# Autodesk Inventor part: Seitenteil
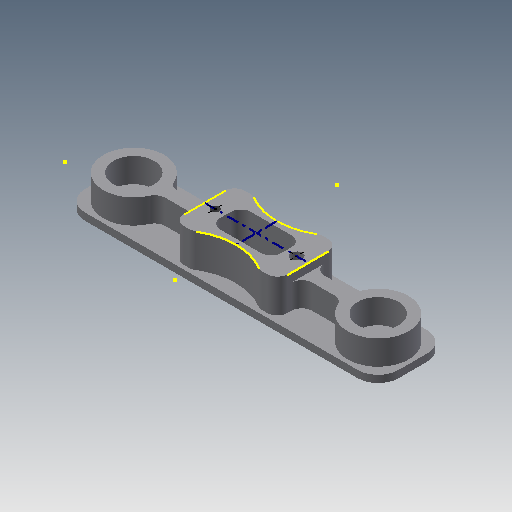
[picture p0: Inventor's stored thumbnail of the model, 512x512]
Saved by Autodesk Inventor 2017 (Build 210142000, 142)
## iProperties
Created: 2015-04
Part Number: Seitenteil
Material: Generisch
Document SubType Name: Modeling
Designer: e_krauts
Density: 1 g/cm^3
Appearance: Vorgabe
Mass: 43.9559 g
Surface Area: 202.761 cm^2
Volume: 43.9559 cm^3
Author: e_krauts
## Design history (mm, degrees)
sketch "Skizze1"
  geometry: L1 (0, 0)-(154, 0); L2 (154, 0)-(154, 34); L3 (154, 34)-(0, 34); L4 (0, 34)-(0, 0)
  constraints: 8 end point, 2 parallel, 1 horizontal, 1 perpendicular
  dimensions: "d0" = 154 distance of L3.end L2.end; "d1" = 34 distance between parallel lines of L3 L1
extrude "Extrusion1" new body sketch "Skizze1" distance "d2" = 3.5; taper "d3" = 0 deg
sketch "Skizze2"
  geometry: L1 (0, 0)-(154, 0) reference; L2 (154, 0)-(154, 34) reference; L3 (154, 34)-(0, 34) reference; L4 (0, 34)-(0, 0) reference; L5 (77, 34)-(77, 0); L6 (0, 17)-(154, 17); L7 (77, 20)-(35.33, 20); L8 (77, 14)-(35.33, 14); L9 (77, 20)-(118.67, 20); L10 (77, 14)-(118.67, 14); L11 (154, 17)-(0, 17); A1 r 5 centre (35.33, 25) between (30.748, 23) and (35.33, 20); A2 r 15 centre (17, 17) between (30.748, 23) and (2, 17); A3 r 5 centre (35.33, 9) between (35.33, 14) and (30.748, 11); A4 r 15 centre (17, 17) between (2, 17) and (30.748, 11); A5 r 5 centre (118.67, 25) between (118.67, 20) and (123.252, 23); A6 r 15 centre (137, 17) between (123.252, 11) and (152, 17); A7 r 15 centre (137, 17) between (152, 17) and (123.252, 23); A8 r 5 centre (118.67, 9) between (123.252, 11) and (118.67, 14)
  constraints: 16 point on circle, 14 end point, 14 symmetric about line, 8 centre point, 5 point on line, 4 midpoint, 2 tangent, 1 parallel, 6 other
  dimensions: "d4" = 6 diameter of L7 L6; "d5" = 15 radius of A2; "d6" = 120 diameter of A2.centre L5; "d7" = 5 radius of A1
extrude "Extrusion2" join sketch "Skizze2" distance "d8" = 12; taper "d9" = 0 deg
sketch "Skizze3"
  geometry: A1 r 15 centre (17, 17) between (30.748, 23) and (30.748, 11) reference; A2 r 15 centre (137, 17) between (123.252, 11) and (123.252, 23) reference; 3 further points
  constraints: 2 coincident
hole "Bohrung1" sketch "Skizze3" at (17, 17), (137, 17) diameter "d10" = 20; stored, may be unused: countersink angle "d14" = 90 deg, drill point angle "d16" = 0 deg; dims "d11" = 6, "d12" = 4, "d13" = 2, "d15" = 12
fillet "Rundung1" dims "d17" = 10
sketch "Skizze4"
  geometry: L1 (144, 34)-(10, 34) reference; L2 (0, 24)-(0, 10) reference; L3 (10, 0)-(144, 0) reference; L4 (154, 10)-(154, 24) reference; L5 (77, 34)-(77, 0); L6 (0, 17)-(154, 17); L7 (102.5, 32)-(51.5, 32); L8 (51.5, 32)-(51.5, 2); L9 (51.5, 2)-(102.5, 2); L10 (102.5, 2)-(102.5, 32); L11 (102.5, 32)-(51.5, 2); L12 (51.5, 32)-(102.5, 2); 2 further points
  constraints: 16 end point, 7 midpoint, 2 parallel, 1 horizontal, 1 perpendicular
  dimensions: "d18" = 51 distance of L9.end L8.end; "d19" = 30 distance of L8.end L7.end
extrude "Extrusion3" join sketch "Skizze4" distance "d20" = 16.5; taper "d21" = 0 deg
fillet "Rundung2" dims "d22" = 5
sketch "Skizze5"
  geometry: L1 (62, 24.5)-(92, 24.5); L2 (92, 24.5)-(92, 9.5); L3 (92, 9.5)-(62, 9.5); L4 (62, 9.5)-(62, 24.5); L5 (62, 24.5)-(92, 9.5); L6 (92, 24.5)-(62, 9.5); 2 further points
  constraints: 12 end point, 2 midpoint, 2 parallel, 1 horizontal, 1 perpendicular
  dimensions: "d23" = 30 distance of L2.end L3.end; "d24" = 15 distance of L1.end L2.end
extrude "Extrusion4" cut sketch "Skizze5" distance "d25" = 16.5; taper "d26" = 0 deg
fillet "Rundung3" dims "d27" = 5
sketch "Skizze6"
  geometry: L1 (51.5, 27)-(51.5, 7) reference; L2 (56.5, 2)-(97.5, 2) reference; L3 (102.5, 7)-(102.5, 27) reference; L4 (97.5, 32)-(56.5, 32) reference; L5 (51.5, 17)-(102.5, 17); L6 (77, 32)-(77, 2); L7 (60.417, 32)-(93.583, 32); L8 (60.417, 2)-(93.583, 2); A1 r 30 centre (77, 57) between (60.417, 32) and (93.583, 32); A2 r 30 centre (77, -23) between (93.583, 2) and (60.417, 2); 1 further point
  constraints: 8 end point, 4 midpoint, 4 point on circle, 3 symmetric about line, 2 centre point, 2 point on line, 1 collinear, 1 other
  dimensions: "d30" = 80 diameter of A1.centre L5; "d31" = 30 radius of A1
extrude "Extrusion5" cut sketch "Skizze6" distance "d32" = 16.5; taper "d33" = 0 deg
fillet "Rundung4" dims "d34" = 5
sketch "Skizze7"
  geometry: L1 (51.5, 27)-(51.5, 7) reference; L2 (102.5, 7)-(102.5, 27) reference; L3 (51.5, 17)-(102.5, 17); L4 (77, 27)-(77, 7); A1 r 30 centre (77, -23) between (92.452, 2.714) and (61.548, 2.714) reference; A2 r 30 centre (77, 57) between (61.548, 31.286) and (92.452, 31.286) reference; 3 further points
  constraints: 4 end point, 2 midpoint, 2 point on circle, 1 point on line, 1 symmetric about line
hole "Bohrung2" sketch "Skizze7" diameter "d36" = 4.134; stored, may be unused: countersink angle "d40" = 90 deg, drill point angle "d42" = 118 deg; dims "d37" = 14, "d38" = 4, "d39" = 2, "d41" = 17
sketch "Skizze9"
  geometry: C1 r 5.2 at (0, 0) reference; 2 further points
  constraints: 1 coincident
hole "Bohrung4" sketch "Skizze9" diameter "d61" = 5.5; stored, may be unused: countersink angle "d65" = 90 deg, drill point angle "d67" = 118 deg; dims "d62" = 6, "d63" = 10.4, "d64" = 2, "d66" = 8
node "Volumenkörper1"
hole "Bohrung3" diameter "d54" = 10.4; stored, may be unused: countersink angle "d58" = 90 deg, drill point angle "d60" = 0 deg; dims "d52" = 17, "d53" = 57, "d55" = 6, "d56" = 4, "d57" = 2, "d59" = 0.5
